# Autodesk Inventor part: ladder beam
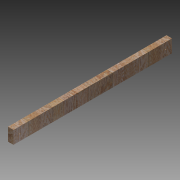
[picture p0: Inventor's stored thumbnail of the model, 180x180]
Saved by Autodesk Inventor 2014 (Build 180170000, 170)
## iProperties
Created: 2013-07
Part Number: ladder beam
Material: Generic
Document SubType Name: Modeling
Designer: Patrick Rice
Density: 1 g/cm^3
Appearance: Red Oak - Natural
Author: Patrick Rice
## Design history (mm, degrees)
sketch "Sketch1"
  geometry: L1 (19.05, -44.45)-(-19.05, -44.45); L2 (-19.05, -44.45)-(-19.05, 44.45); L3 (-19.05, 44.45)-(19.05, 44.45); L4 (19.05, 44.45)-(19.05, -44.45); L5 (19.05, -44.45)-(-19.05, 44.45); L6 (-19.05, -44.45)-(19.05, 44.45); 1 further point
  constraints: 12 end point, 2 midpoint, 2 parallel, 1 horizontal, 1 perpendicular
  dimensions: "d0" = 38.1 distance of L2.end L3.end; "d1" = 88.9 distance of L3.end L1.start
extrude "Extrusion1" new body sketch "Sketch1" distance "d2" = 1092.2; taper "d3" = 0 deg
hole "Hole1" diameter "d6" = 6.35; stored, may be unused: countersink angle "d10" = 82 deg, drill point angle "d12" = 118 deg; dims "d4" = 44.45, "d5" = 44.45, "d7" = 19.05, "d8" = 9.525, "d9" = 6.35, "d11" = 25.4
hole "Hole2" diameter "d15" = 6.35; stored, may be unused: countersink angle "d19" = 82 deg, drill point angle "d21" = 118 deg; dims "d13" = 44.45, "d14" = 44.45, "d16" = 19.05, "d17" = 9.525, "d18" = 6.35, "d20" = 25.4
body "Solid1"
